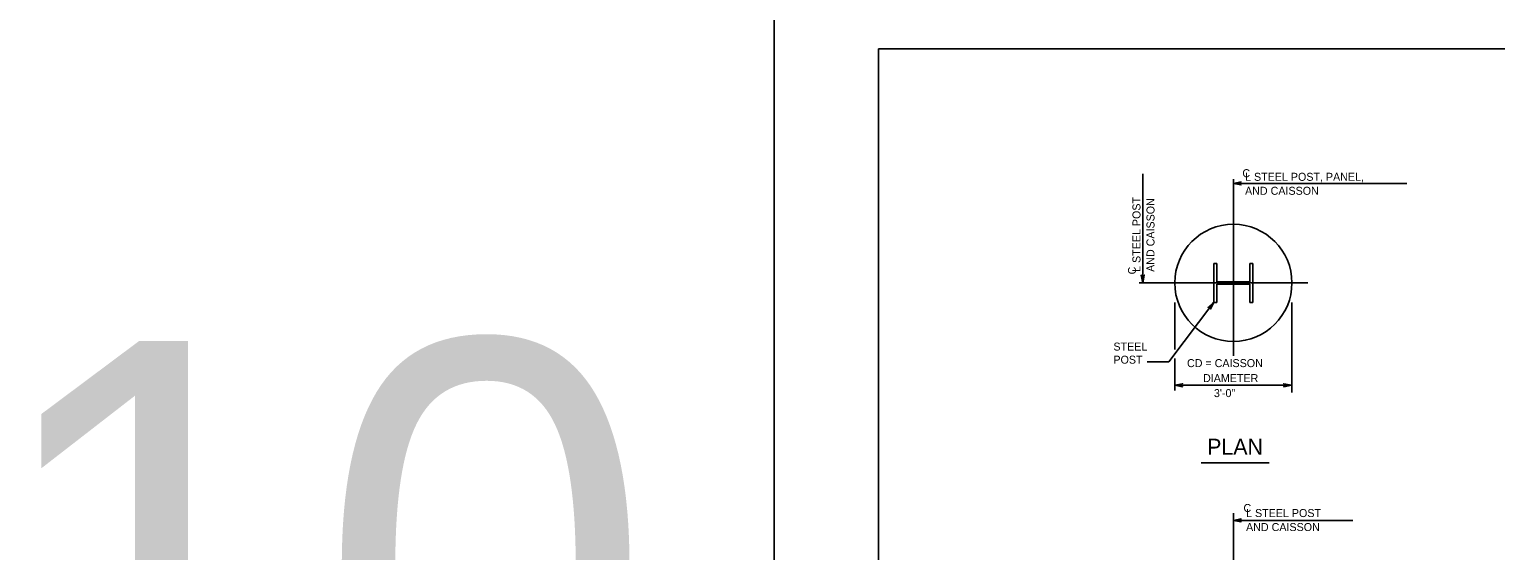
# Model space of a CAD drawing. Extents: x 3475 to 6558, y -3780 to 1166.
# Drawn here: x 3475 to 4038, y -1418 to -1218 of the extents above; entities that cross this region are included whole.
import ezdxf

# ---------------------------------------------------------------- set-up
doc = ezdxf.new("R2010")
doc.units = 0
for name, color, linetype in [('1', 7, 'Continuous'), ('2', 7, 'Continuous'), ('PLT-BNDY', 7, 'Continuous')]:
    doc.layers.add(name, color=color, linetype=linetype)

msp = doc.modelspace()

# ---------------------------------------------------------------- linework, layer by layer
at = {"layer": '1'}
for p, q in [((3902.78, -1273.32), (3902.78, -1315.24)), ((3937.55, -1275.42), (3937.55, -1343.21)), ((3937.55, -1277.03), (4004.11, -1277.03)), ((3930.05, -1322.74), (3930.05, -1307.74)), ((3930.05, -1307.74), (3931.18, -1307.74)), ((3931.17, -1314.81), (3931.18, -1307.74)), ((3943.93, -1307.74), (3945.05, -1307.74)), ((3943.93, -1314.81), (3943.93, -1307.74)), ((3945.05, -1322.74), (3945.05, -1307.74)), ((3901.36, -1315.24), (3966.17, -1315.24)), ((3943.93, -1314.81), (3931.17, -1314.81)), ((3931.17, -1322.74), (3931.18, -1315.68)), ((3943.92, -1315.67), (3931.18, -1315.68)), ((3943.92, -1322.74), (3943.92, -1315.67)), ((3930.05, -1322.74), (3931.18, -1322.74)), ((3943.93, -1322.74), (3945.05, -1322.74)), ((3915.05, -1322.79), (3915.05, -1340.82)), ((3960.05, -1322.79), (3960.05, -1357.32)), ((3915.05, -1344.29), (3915.05, -1356.63)), ((3915.05, -1354.57), (3959.86, -1354.57)), ((3925.16, -1384.34), (3951.32, -1384.34)), ((3937.55, -1403.75), (3937.55, -1600.18)), ((3937.55, -1406.48), (3983.36, -1406.48))]:
    msp.add_line(p, q, dxfattribs=at)
for points in [[(3937.55, -1277.03), (3940.53, -1276.47), (3940.3, -1276.63), (3940.18, -1276.83), (3940.15, -1277.03), (3940.18, -1277.23), (3940.3, -1277.43), (3940.53, -1277.59), (3937.55, -1277.03), (3940.3, -1277.43), (3940.18, -1277.23), (3937.55, -1277.03), (3940.15, -1277.03), (3940.18, -1276.83), (3937.55, -1277.03), (3940.3, -1276.63)], [(3902.78, -1315.24), (3902.22, -1312.26), (3902.38, -1312.49), (3902.58, -1312.61), (3902.78, -1312.64), (3902.98, -1312.61), (3903.18, -1312.49), (3903.34, -1312.26), (3902.78, -1315.24), (3903.18, -1312.49), (3902.98, -1312.61), (3902.78, -1315.24), (3902.78, -1312.64), (3902.58, -1312.61), (3902.78, -1315.24), (3902.38, -1312.49)], [(3904.41, -1345.57), (3912.78, -1345.57), (3930.11, -1322.61)], [(3930.11, -1322.61), (3928.76, -1325.32), (3928.77, -1325.05), (3928.68, -1324.83), (3928.55, -1324.68), (3928.36, -1324.59), (3928.13, -1324.56), (3927.87, -1324.65), (3930.11, -1322.61), (3928.13, -1324.56), (3928.36, -1324.59), (3930.11, -1322.61), (3928.55, -1324.68), (3928.68, -1324.83), (3930.11, -1322.61), (3928.77, -1325.05)], [(3915.05, -1354.57), (3918.03, -1354.01), (3917.8, -1354.17), (3917.68, -1354.37), (3917.65, -1354.57), (3917.68, -1354.77), (3917.8, -1354.97), (3918.03, -1355.13), (3915.05, -1354.57), (3917.8, -1354.97), (3917.68, -1354.77), (3915.05, -1354.57), (3917.65, -1354.57), (3917.68, -1354.37), (3915.05, -1354.57), (3917.8, -1354.17)], [(3959.86, -1354.57), (3956.88, -1355.13), (3957.11, -1354.97), (3957.23, -1354.77), (3957.26, -1354.57), (3957.23, -1354.37), (3957.11, -1354.17), (3956.88, -1354.01), (3959.86, -1354.57), (3957.11, -1354.17), (3957.23, -1354.37), (3959.86, -1354.57), (3957.26, -1354.57), (3957.23, -1354.77), (3959.86, -1354.57), (3957.11, -1354.97)], [(3937.55, -1406.48), (3940.53, -1405.92), (3940.3, -1406.08), (3940.18, -1406.28), (3940.15, -1406.48), (3940.18, -1406.68), (3940.3, -1406.88), (3940.53, -1407.04), (3937.55, -1406.48), (3940.3, -1406.88), (3940.18, -1406.68), (3937.55, -1406.48), (3940.15, -1406.48), (3940.18, -1406.28), (3937.55, -1406.48), (3940.3, -1406.08)]]:
    msp.add_lwpolyline(points, dxfattribs=at)
msp.add_circle((3937.55, -1315.24), 22.5, dxfattribs=at)
at = {"layer": '2'}
for p, q in [((3801.34, -1789.31), (3801.34, -1225.31)), ((3801.34, -1225.31), (4587.34, -1225.31))]:
    msp.add_line(p, q, dxfattribs=at)
at = {"layer": 'PLT-BNDY'}
msp.add_lwpolyline([(3761.34, -1210.31), (4602.34, -1210.31), (4602.34, -1804.31), (3761.34, -1804.31)], close=True, dxfattribs=at)

# ---------------------------------------------------------------- texts
at = {"layer": '1'}
for s, height, p in [('C', 3.07, (3941.02, -1274.63)), ('L STEEL POST, PANEL, ', 3.072, (3942.04, -1276.02)), ('AND CAISSON', 3.072, (3942.04, -1281.39)), ('10', 172.802, (3457.76, -1510.33)), ('STEEL', 3.072, (3891.51, -1341.25)), ('POST', 3.072, (3891.51, -1346.29)), ('CD = CAISSON', 3.072, (3919.76, -1347.6)), ('DIAMETER', 3.072, (3925.91, -1353.36)), ('3\'-0"', 3.072, (3930.09, -1359.12)), ('PLAN', 6.144, (3927.47, -1381.27)), ('C', 3.07, (3941.44, -1403.27)), ('L STEEL POST', 3.072, (3942.43, -1405.21)), ('AND CAISSON', 3.072, (3942.43, -1410.59))]:
    msp.add_text(s, height=height, dxfattribs=at).set_placement(p)
for s, height, p in [('L STEEL POST', 3.072, (3901.9, -1311.01)), ('AND CAISSON', 3.072, (3907.28, -1311.01)), ('C', 3.07, (3900.19, -1311.98))]:
    msp.add_text(s, height=height, rotation=90, dxfattribs=at).set_placement(p)

doc.saveas('drawing.dxf')
